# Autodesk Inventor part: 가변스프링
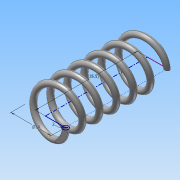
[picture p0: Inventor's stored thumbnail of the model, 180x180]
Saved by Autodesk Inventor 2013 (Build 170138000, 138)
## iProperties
Created: 2020-02
Part Number: 가변스프링
Material: 강철
Document SubType Name: Modeling
Designer: Administrator
Density: 7.85 g/cm^3
Mass: 7.34877 g
Surface Area: 18.955 cm^2
Volume: 0.936149 cm^3
Author: Administrator
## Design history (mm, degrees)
sketch "스케치1"
  geometry: L1 (0, 0)-(7, 0); L2 (7, 0)-(7, 35.5); L3 (7, 35.5)-(0, 35.5); L4 (0, 35.5)-(0, 0); C1 r 1 at (7, 0)
  constraints: 8 end point, 2 parallel, 1 centre point, 1 coincident, 1 horizontal, 1 perpendicular
  dimensions: "d0" = 2 diameter of C1; "d1" = 14 diameter of L2 L4; "d2" = 35.5 distance of L3.end L1.start (derived)
feature "코일1" sketch "스케치1" pitch "d3" = 10; turns "d5" = 6; dims "d4" = 35.5 (= d2), "d6" = 0, angle "d7" = 90 deg, angle "d8" = 90 deg, "d9" = 0, "d10" = 0
sketch "스케치2"
  geometry: L1 (0, 0)-(35.5, 0); L2 (35.5, 0)-(35.5, -13); L3 (35.5, -13)-(0, -13); L4 (0, -13)-(0, 0)
  constraints: 8 end point, 2 parallel, 1 horizontal, 1 perpendicular
  dimensions: "d11" = 35.5 distance of L1.start L1.end (= d2); "d12" = 13 distance between parallel lines of L3 L1
revolve "회전1" sketch "스케치2" stored, may be unused: angle "d13" = 90 deg
node "솔리드1"
